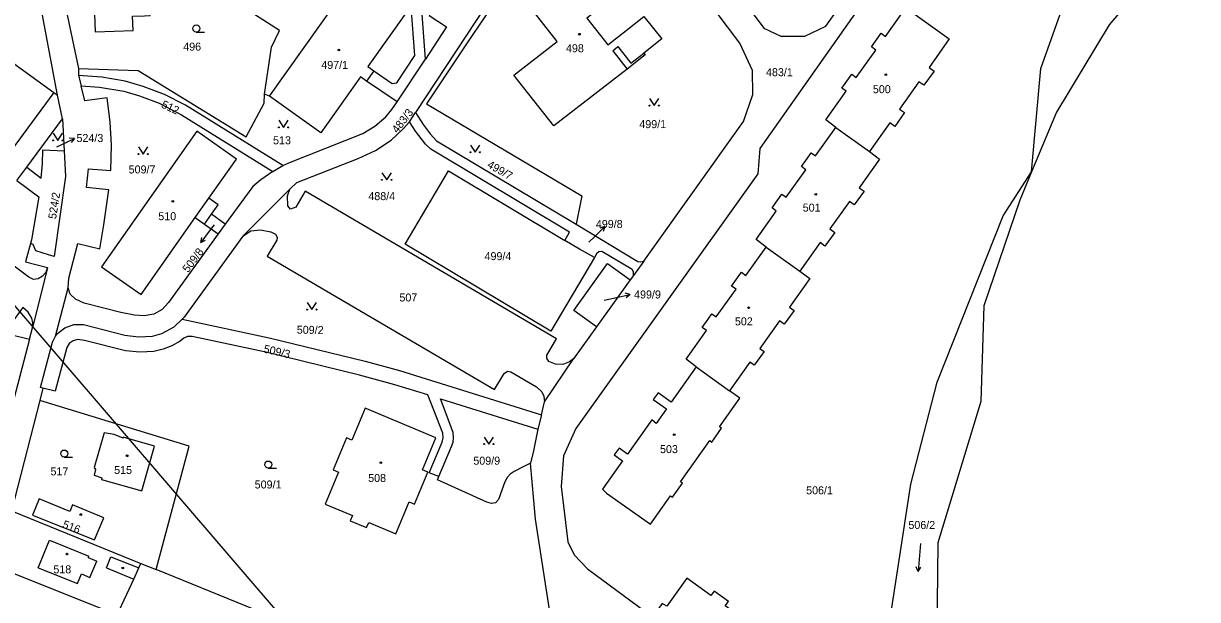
# Model space of a CAD drawing. Extents: x -558358 to -557517, y -1073785 to -1073189.
# Drawn here: x -558075.5 to -557826.1, y -1073555.9 to -1073433.5 of the extents above; entities that cross this region are included whole.
import ezdxf

# ---------------------------------------------------------------- set-up
doc = ezdxf.new("R2010")
doc.units = 0
for name, color, linetype in [('Hranice parcel', 7, 'Continuous'), ('Parcelní čísla', 7, 'Continuous'), ('Pop  PČ popisy', 7, 'Continuous'), ('Vnitřní kresba', 7, 'Continuous'), ('Vrstva 28', 7, 'Continuous'), ('Značky budov', 7, 'Continuous'), ('Značky kultur', 7, 'Continuous')]:
    doc.layers.add(name, color=color, linetype=linetype)

msp = doc.modelspace()

# ---------------------------------------------------------------- linework, layer by layer
at = {"layer": 'Hranice parcel'}
for p, q in [((-558068.26, -1073448.76), (-558079.07, -1073390.9)), ((-558069.9, -1073413.89), (-558063.79, -1073443.12)), ((-558079.09, -1073440.91), (-558069.01, -1073448.19)), ((-557996.12, -1073450.19), (-557990.11, -1073441.11)), ((-558063.79, -1073443.12), (-558063.8, -1073444.57)), ((-558063.8, -1073444.57), (-558063.26, -1073446.76)), ((-558001.05, -1073443.62), (-558002.62, -1073445.83)), ((-558001.05, -1073443.62), (-557997.16, -1073446.28)), ((-557996.12, -1073450.19), (-558002.62, -1073445.83)), ((-558069.01, -1073448.19), (-558068.26, -1073448.76)), ((-558067.19, -1073453.76), (-558068.26, -1073448.76)), ((-558023.22, -1073448.98), (-558024.27, -1073448.53)), ((-558074.8, -1073464.07), (-558067.19, -1073453.76)), ((-558067.19, -1073453.76), (-558066.82, -1073460.61)), ((-557993.5, -1073454.4), (-557992.19, -1073452.45)), ((-557902.93, -1073455.63), (-557895.8, -1073460.74)), ((-557987.76, -1073458.45), (-557958.11, -1073476.19)), ((-558071.37, -1073460.39), (-558066.82, -1073460.61)), ((-558076.9, -1073466.92), (-558074.8, -1073464.07)), ((-558074.8, -1073464.07), (-558071.72, -1073466.37)), ((-558022.54, -1073464.96), (-558020.42, -1073463.73)), ((-558076.9, -1073466.92), (-558072.2, -1073470.34)), ((-558018.89, -1073468.72), (-558028.88, -1073478.68)), ((-558072.2, -1073470.34), (-558073.77, -1073479.5)), ((-558037.01, -1073476.18), (-558035.54, -1073474.05)), ((-558032.65, -1073476.17), (-558035.54, -1073474.05)), ((-558037.01, -1073476.18), (-558034.12, -1073478.2)), ((-558032.65, -1073476.17), (-558034.12, -1073478.2)), ((-557958.11, -1073476.19), (-557944.96, -1073484.06)), ((-558073.77, -1073479.5), (-558073.98, -1073480.28)), ((-558073.98, -1073480.28), (-558075.03, -1073484.15)), ((-557917.76, -1073481.02), (-557910.62, -1073486.13)), ((-558075.03, -1073484.15), (-558070.38, -1073485.35)), ((-557958.62, -1073494.5), (-557951.44, -1073484.51)), ((-557951.44, -1073484.51), (-557946.6, -1073487.99)), ((-557943.74, -1073483.99), (-557945.94, -1073487.07)), ((-557944.96, -1073484.06), (-557944.51, -1073484.17)), ((-557944.51, -1073484.17), (-557943.74, -1073483.99)), ((-558070.38, -1073485.35), (-558073.57, -1073498.15)), ((-557945.94, -1073487.07), (-557946.6, -1073487.99)), ((-557945.94, -1073487.07), (-557945.95, -1073486.25)), ((-558068.7, -1073499.98), (-558066, -1073489.71)), ((-557946.6, -1073487.99), (-557953.75, -1073497.99)), ((-557953.75, -1073497.99), (-557958.62, -1073494.5)), ((-558078.27, -1073499.57), (-558074.22, -1073500.6)), ((-558074.22, -1073500.6), (-558073.57, -1073498.15)), ((-557953.75, -1073497.99), (-557958.67, -1073504.77)), ((-558074.22, -1073500.6), (-558078.34, -1073516.28)), ((-557964.79, -1073513.87), (-557958.67, -1073504.77)), ((-557932.61, -1073506.45), (-557925.51, -1073511.53)), ((-558071.35, -1073510.96), (-558072, -1073513.63)), ((-558071.35, -1073510.96), (-558071.87, -1073510.83)), ((-558068.72, -1073511.63), (-558071.35, -1073510.96)), ((-558072, -1073513.63), (-558078.01, -1073537.04)), ((-557965.43, -1073516.64), (-557964.79, -1073513.87)), ((-557872.13, -1073513.82), (-557881.3, -1073543.83)), ((-557965.43, -1073516.64), (-557966.22, -1073519.7)), ((-557966.22, -1073519.7), (-557967.17, -1073524.31)), ((-557967.17, -1073524.31), (-557967.76, -1073526.9)), ((-557967.76, -1073526.9), (-557969.49, -1073527.78)), ((-558078.01, -1073537.04), (-558050.57, -1073548.21)), ((-558080.96, -1073549.01), (-558055.56, -1073559.09)), ((-558050.57, -1073548.21), (-558047.33, -1073549.53))]:
    msp.add_line(p, q, dxfattribs=at)
for points in [[(-558022.09, -1073311.21), (-558020.08, -1073313.87), (-558000.41, -1073328.2), (-557993.92, -1073334.5), (-557986.04, -1073343.93), (-557967.1, -1073369.2), (-557918.24, -1073434.51), (-557914.64, -1073436.24), (-557909.55, -1073436.22), (-557905.05, -1073434.1), (-557902.57, -1073430.65), (-557891.22, -1073414.37), (-557877.97, -1073395.43)], [(-557997.16, -1073446.28), (-557996.18, -1073446.14), (-557992.37, -1073440.37), (-557993.13, -1073429.99), (-557993.58, -1073428.02), (-558004.25, -1073395), (-558005.55, -1073391.58), (-558006.57, -1073389.94), (-558009.69, -1073386.81), (-558015.69, -1073381.13), (-558022.86, -1073375.1), (-558038.38, -1073364.54), (-558051.46, -1073355.75)], [(-557861.36, -1073465.07), (-557859.38, -1073443.12), (-557853.44, -1073426.35), (-557845.8, -1073410.81), (-557826.12, -1073387.26)], [(-557990.11, -1073441.11), (-557990.95, -1073429.72), (-557991.6, -1073426.99), (-558000.34, -1073399.97), (-557986.42, -1073409.86), (-557979.13, -1073399.38), (-557977.23, -1073400.7), (-557975.75, -1073398.59), (-557966.19, -1073404.96)], [(-557943.74, -1073483.99), (-557922.57, -1073454.37), (-557920.54, -1073448.62), (-557920.67, -1073443.5), (-557923.32, -1073437.76), (-557933.57, -1073424.07), (-557935, -1073422.19), (-557950.81, -1073400.97)], [(-557966.19, -1073404.96), (-557967.15, -1073406.3), (-557970.9, -1073403.86), (-557989.34, -1073431.82), (-557985.62, -1073434.28), (-557990.11, -1073441.11)], [(-557960.73, -1073418.81), (-557955.07, -1073414.41), (-557951.22, -1073411.42), (-557950.93, -1073411.8), (-557947.21, -1073416.59), (-557951.08, -1073419.63), (-557946.63, -1073425.3), (-557955.8, -1073432.39), (-557951.37, -1073438.08), (-557947.44, -1073435.04), (-557943.73, -1073432.04), (-557939.89, -1073436.78), (-557943.7, -1073439.86), (-557943.42, -1073440.21), (-557947.29, -1073443.23), (-557962.81, -1073455.3), (-557971.36, -1073444.52), (-557962.13, -1073437.38), (-557970.6, -1073426.47), (-557970.03, -1073426.04)], [(-557875.08, -1073418.52), (-557880.11, -1073415), (-557884.66, -1073414.11), (-557888.78, -1073417.07), (-557919.08, -1073460.09), (-557919.51, -1073465.45), (-557958.15, -1073519.56), (-557960.76, -1073525.37), (-557961.25, -1073531.9), (-557959.85, -1073543.64), (-557958.52, -1073546.41), (-557955.67, -1073549.33), (-557941.9, -1073559.58)], [(-557968.81, -1073419.39), (-557969.8, -1073419.14), (-557970.66, -1073419.77), (-557992.19, -1073452.45)], [(-558049.8, -1073431.93), (-558048.54, -1073431.88), (-558048.64, -1073429.15), (-558049.91, -1073429.2), (-558050.08, -1073422.86), (-558052.56, -1073422.66), (-558052.57, -1073422.02), (-558060.76, -1073422.24), (-558060.26, -1073435.32), (-558052.21, -1073435.02), (-558052.32, -1073432.02), (-558049.8, -1073431.93)], [(-557834.15, -1073421.11), (-557844.86, -1073433.81), (-557856.07, -1073452.41), (-557861.36, -1073465.07)], [(-558023.22, -1073448.98), (-558004.82, -1073423.06), (-557993.94, -1073430.83), (-558002.36, -1073442.69), (-558001.05, -1073443.62)], [(-557971.99, -1073423.64), (-557977.49, -1073432.15), (-557981.25, -1073437.64), (-557989.89, -1073450.63)], [(-558024.27, -1073448.53), (-558022.77, -1073438.58), (-558021.1, -1073435.02), (-558027.22, -1073431.17)], [(-557902.93, -1073455.63), (-557905.05, -1073454), (-557900.72, -1073447.94), (-557901.66, -1073447.27), (-557899.55, -1073444.33), (-557898.62, -1073444.99), (-557894.46, -1073439.18), (-557895.4, -1073438.51), (-557893.33, -1073435.61), (-557892.39, -1073436.28), (-557888.07, -1073430.23), (-557878.84, -1073436.82), (-557883.15, -1073442.9), (-557882.08, -1073443.65), (-557884.22, -1073446.66), (-557885.28, -1073445.91), (-557889.41, -1073451.73), (-557888.35, -1073452.48), (-557890.43, -1073455.41), (-557891.49, -1073454.66), (-557895.8, -1073460.74)], [(-558020.42, -1073463.73), (-558041.1, -1073450.88), (-558045.53, -1073448.61), (-558050.06, -1073446.9), (-558053.87, -1073445.77), (-558058.84, -1073444.97), (-558063.8, -1073444.57)], [(-558063.79, -1073443.12), (-558051.12, -1073443.51), (-558028.21, -1073457.62), (-558024.35, -1073450.45), (-558024.27, -1073448.53)], [(-558002.62, -1073445.83), (-558003.93, -1073444.91), (-558012.33, -1073456.75), (-558023.22, -1073448.98)], [(-558066, -1073489.71), (-558065.83, -1073487.66), (-558063.93, -1073480.27), (-558059.28, -1073481.39), (-558058.41, -1073476.28), (-558057.32, -1073468.85), (-558062.09, -1073468.41), (-558061.69, -1073464.41), (-558056.9, -1073464.79), (-558056.8, -1073459.32), (-558057.06, -1073454.51), (-558057.72, -1073449.34), (-558062.47, -1073450), (-558063.26, -1073446.76)], [(-558063.26, -1073446.76), (-558059.34, -1073447.1), (-558054.18, -1073447.94), (-558050.82, -1073448.92), (-558046.65, -1073450.5), (-558041.92, -1073452.93), (-558022.54, -1073464.96)], [(-558069.01, -1073448.19), (-558089.39, -1073475.8), (-558089.17, -1073475.95), (-558090.09, -1073477.27), (-558100.29, -1073469.58), (-558095.61, -1073463.24)], [(-558020.42, -1073463.73), (-558018.76, -1073463.03), (-558003.4, -1073456.89), (-558000.84, -1073455.32), (-557998.53, -1073453.34), (-557997.26, -1073451.83), (-557996.12, -1073450.19)], [(-557989.89, -1073450.63), (-557956.91, -1073470.13), (-557958.11, -1073476.19)], [(-558018.89, -1073468.72), (-558017.43, -1073467.28), (-558004.36, -1073462.2), (-558000.71, -1073460.54), (-557997.38, -1073458.33), (-557994.81, -1073455.9), (-557993.5, -1073454.4)], [(-557960.53, -1073479.61), (-557959.52, -1073477.88), (-557988.99, -1073460.22), (-557990.09, -1073459.14), (-557992.19, -1073456.42), (-557993.5, -1073454.4)], [(-557992.19, -1073452.45), (-557990.57, -1073454.98), (-557989.11, -1073456.98), (-557987.76, -1073458.45)], [(-558035.54, -1073474.05), (-558034.14, -1073472.03), (-558036.08, -1073470.66), (-558030.24, -1073462.37), (-558038.66, -1073456.4), (-558058.9, -1073485.25), (-558050.49, -1073491.12), (-558038.98, -1073474.78), (-558037.01, -1073476.18)], [(-557917.76, -1073481.02), (-557919.89, -1073479.42), (-557915.58, -1073473.37), (-557916.49, -1073472.72), (-557914.4, -1073469.79), (-557913.49, -1073470.44), (-557909.33, -1073464.6), (-557910.24, -1073463.95), (-557908.96, -1073462.17), (-557908.15, -1073461.02), (-557907.24, -1073461.67), (-557902.93, -1073455.63)], [(-558066.82, -1073460.61), (-558066.53, -1073466.05), (-558068.98, -1073483.05), (-558070.17, -1073482.68), (-558072.89, -1073481.86), (-558073.42, -1073480.5), (-558073.98, -1073480.28)], [(-558071.72, -1073466.37), (-558071.45, -1073463.36), (-558071.37, -1073460.39)], [(-557895.8, -1073460.74), (-557893.65, -1073462.39), (-557897.97, -1073468.43), (-557896.94, -1073469.17), (-557899.02, -1073472.08), (-557900.05, -1073471.34), (-557904.22, -1073477.17), (-557903.16, -1073477.93), (-557905.25, -1073480.84), (-557906.3, -1073480.09), (-557910.62, -1073486.13)], [(-557954.23, -1073483.22), (-557963.48, -1073498.87), (-557994.38, -1073480.4), (-557985.2, -1073464.81), (-557960.53, -1073479.61)], [(-558022.54, -1073464.96), (-558025.08, -1073466.74), (-558026.8, -1073468.19), (-558032.65, -1073476.17)], [(-557897.48, -1073592.57), (-557892.38, -1073566.43), (-557887.02, -1073531.37), (-557881.44, -1073509.74), (-557867.37, -1073474.4), (-557861.36, -1073465.07)], [(-557861.36, -1073465.07), (-557863.88, -1073471.1), (-557871.54, -1073493.51), (-557872.13, -1073513.82)], [(-557958.67, -1073504.77), (-557959.52, -1073505.42), (-557960.94, -1073505.97), (-557962.48, -1073505.9), (-557963.93, -1073505.3), (-557964.34, -1073504.64), (-557964.29, -1073503.98), (-557962.25, -1073500.52), (-558015.64, -1073469.14), (-558017.62, -1073472.56), (-558018.8, -1073472.98), (-558019.32, -1073472.29), (-558019.38, -1073470.18), (-558018.89, -1073468.72)], [(-558073.57, -1073498.15), (-558073.51, -1073497.13), (-558073.7, -1073496.11), (-558074.52, -1073494.85), (-558075.64, -1073493.89), (-558078.28, -1073497.56), (-558092.71, -1073486.96), (-558086.45, -1073478.46)], [(-558070.38, -1073485.35), (-558070.76, -1073486.43), (-558071.41, -1073487.24), (-558072.33, -1073487.8), (-558073.38, -1073487.88), (-558074.36, -1073487.41), (-558086.45, -1073478.46)], [(-558034.12, -1073478.2), (-558044.67, -1073492.79), (-558046.03, -1073494.25), (-558047.82, -1073495.28), (-558049.88, -1073495.66), (-558051.92, -1073495.51), (-558054.81, -1073494.91), (-558062.59, -1073492.91), (-558064.44, -1073492.11), (-558065.56, -1073491.04), (-558066, -1073489.71)], [(-558028.88, -1073478.68), (-558041.38, -1073495.88), (-558041.79, -1073496.35)], [(-558028.88, -1073478.68), (-558027.22, -1073477.58), (-558025.14, -1073477.37), (-558022.91, -1073477.77), (-558021.94, -1073478.27), (-558021.58, -1073478.9), (-558021.69, -1073479.54), (-558023.7, -1073482.95), (-557975.42, -1073511.29), (-557973.41, -1073507.84), (-557972.71, -1073507.36), (-557971.95, -1073507.53), (-557966.49, -1073510.72), (-557965.39, -1073511.77), (-557964.96, -1073512.7), (-557964.79, -1073513.87)], [(-557954.23, -1073483.22), (-557957.38, -1073481.46), (-557960.53, -1073479.61)], [(-557945.95, -1073486.25), (-557946.2, -1073485.81), (-557952.65, -1073481.96), (-557953.3, -1073482.07), (-557953.78, -1073482.47), (-557954.23, -1073483.22)], [(-557932.61, -1073506.45), (-557934.75, -1073504.84), (-557930.41, -1073498.76), (-557931.35, -1073498.09), (-557930.07, -1073496.31), (-557929.28, -1073495.19), (-557928.34, -1073495.86), (-557924.14, -1073489.96), (-557925.07, -1073489.3), (-557922.99, -1073486.39), (-557922.06, -1073487.05), (-557917.76, -1073481.02)], [(-557910.62, -1073486.13), (-557908.48, -1073487.72), (-557912.81, -1073493.77), (-557911.82, -1073494.47), (-557913.92, -1073497.39), (-557914.9, -1073496.69), (-557919.09, -1073502.55), (-557918.19, -1073503.19), (-557920.29, -1073506.11), (-557921.18, -1073505.47), (-557925.51, -1073511.53)], [(-558068.7, -1073499.98), (-558068.26, -1073499.37), (-558066.7, -1073498.15), (-558064.79, -1073497.48), (-558062.72, -1073497.49), (-558053.98, -1073499.73), (-558051.03, -1073500.12), (-558048.06, -1073499.96), (-558046.1, -1073499.41), (-558043.49, -1073497.93), (-558041.79, -1073496.35)], [(-558041.79, -1073496.35), (-558023.3, -1073500.28), (-558002.91, -1073505.27), (-557995.6, -1073507.26), (-557965.43, -1073516.64)], [(-558071.87, -1073510.83), (-558069.32, -1073501.19), (-558068.7, -1073499.98)], [(-557987.27, -1073529.77), (-557989.29, -1073528.94), (-557986.56, -1073522.48), (-557986.36, -1073521.52), (-557986.44, -1073520.51), (-557989.6, -1073512.4), (-557996.64, -1073510.25), (-558004.14, -1073508.22), (-558024.01, -1073503.35), (-558039.66, -1073500.03), (-558040.64, -1073500.03), (-558041.42, -1073500.4), (-558042.23, -1073501), (-558043.97, -1073502.01), (-558045.84, -1073502.74), (-558047.8, -1073503.22), (-558050.8, -1073503.37), (-558053.79, -1073503.03), (-558062.52, -1073500.9), (-558063.99, -1073500.68), (-558064.96, -1073500.91), (-558065.77, -1073501.48), (-558066.28, -1073502.33), (-558068.72, -1073511.63)], [(-557932.61, -1073506.45), (-557937.92, -1073513.94), (-557940.69, -1073511.97), (-557941.71, -1073513.4), (-557938.93, -1073515.37), (-557941.12, -1073518.46), (-557942.01, -1073517.7), (-557947.21, -1073524.97), (-557948.97, -1073523.73), (-557949.99, -1073525.17), (-557948.24, -1073526.41), (-557952.49, -1073532.47), (-557951.63, -1073533.27), (-557942.33, -1073539.86), (-557938.05, -1073533.83), (-557937.62, -1073534.14), (-557935.52, -1073531.19), (-557935.95, -1073530.88), (-557929.72, -1073522.11), (-557929.27, -1073522.43), (-557927.19, -1073519.5), (-557927.64, -1073519.19), (-557923.33, -1073513.13), (-557925.51, -1073511.53)], [(-558047.33, -1073549.53), (-558040.31, -1073523.33), (-558072, -1073513.63)], [(-557987.27, -1073529.77), (-557984.55, -1073523.36), (-557984.23, -1073522.42), (-557984.14, -1073521.45), (-557984.2, -1073520.39), (-557986.94, -1073513.23), (-557966.22, -1073519.7)], [(-558008.57, -1073528.8), (-558011.42, -1073535.59), (-558005.63, -1073538.02), (-558006.1, -1073539.13), (-558002.62, -1073540.59), (-558002.16, -1073539.49), (-557996.41, -1073541.91), (-557993.56, -1073535.14), (-557992.45, -1073535.6), (-557989.61, -1073528.81), (-557990.71, -1073528.34), (-557987.91, -1073521.54), (-558002.9, -1073515.24), (-558005.74, -1073522.02), (-558006.84, -1073521.56), (-558009.68, -1073528.33), (-558008.57, -1073528.8)], [(-558060.16, -1073528.26), (-558060.48, -1073529.48), (-558058.86, -1073530.06), (-558058.94, -1073530.35), (-558050.37, -1073532.81), (-558047.63, -1073523.32), (-558054.29, -1073521.4), (-558054.34, -1073521.59), (-558056.23, -1073520.85), (-558058.32, -1073520.45), (-558060.47, -1073527.85), (-558060.16, -1073528.26)], [(-557961.12, -1073576.24), (-557962.13, -1073568.62), (-557962.94, -1073563.5), (-557966.76, -1073538.79), (-557967.76, -1073526.9)], [(-557969.49, -1073527.78), (-557971.24, -1073528.71), (-557972.09, -1073529.24), (-557972.78, -1073529.97), (-557973.26, -1073530.86), (-557974.57, -1073534.63), (-557975.26, -1073535.31), (-557976.1, -1073535.45), (-557977.05, -1073535.17), (-557987.55, -1073530.47), (-557987.27, -1073529.77)], [(-558058.43, -1073538.53), (-558065.06, -1073535.79), (-558065.61, -1073537.16), (-558072.15, -1073534.51), (-558073.59, -1073537.94), (-558060.37, -1073543.23), (-558058.43, -1073538.53)], [(-557881.3, -1073543.83), (-557881.54, -1073569.39), (-557886.18, -1073582.51)], [(-558055.56, -1073559.09), (-558052.02, -1073551.52), (-558051, -1073549.15), (-558050.57, -1073548.21)], [(-557977.41, -1073591.02), (-557981.5, -1073577.12), (-557984.25, -1073575.17), (-558047.33, -1073549.53)], [(-557944.07, -1073562.64), (-557943.15, -1073563.3), (-557947.42, -1073569.28), (-557934.16, -1073578.7), (-557929.93, -1073572.77), (-557928.96, -1073573.46), (-557924.72, -1073567.52), (-557925.63, -1073566.74), (-557921.33, -1073560.9), (-557926.44, -1073557.23), (-557925.76, -1073556.27), (-557928.81, -1073554.08), (-557929.5, -1073555.03), (-557934.61, -1073551.36), (-557938.85, -1073557.29), (-557939.81, -1073556.68), (-557941.9, -1073559.58)]]:
    msp.add_lwpolyline(points, dxfattribs=at)
at = {"layer": 'Pop  PČ popisy'}
for p, q in [((-558068.37, -1073459.77), (-558067.34, -1073459.26)), ((-558067.34, -1073459.26), (-558064.64, -1073457.94)), ((-558064.64, -1073457.94), (-558065.76, -1073457.93)), ((-558064.64, -1073457.94), (-558065.32, -1073458.83)), ((-558035, -1073476.29), (-558036.02, -1073477.67)), ((-557954.15, -1073478.76), (-557951.99, -1073476.68)), ((-557951.99, -1073476.68), (-557953.06, -1073477.01)), ((-557951.99, -1073476.68), (-557952.36, -1073477.73)), ((-558036.02, -1073477.67), (-558037.83, -1073480.07)), ((-558037.83, -1073480.07), (-558037.62, -1073478.97)), ((-558037.83, -1073480.07), (-558036.82, -1073479.57)), ((-557955.41, -1073479.99), (-557954.15, -1073478.76)), ((-557952.15, -1073492.28), (-557949.53, -1073491.73)), ((-557949.53, -1073491.73), (-557946.59, -1073491.11)), ((-557946.59, -1073491.11), (-557947.68, -1073490.82)), ((-557946.59, -1073491.11), (-557947.47, -1073491.8))]:
    msp.add_line(p, q, dxfattribs=at)
at = {"layer": 'Vnitřní kresba'}
for p, q in [((-557950.33, -1073439.32), (-557949.26, -1073438.42)), ((-557950.33, -1073439.32), (-557947.29, -1073443.23)), ((-557949.26, -1073438.42), (-557946.5, -1073442)), ((-557946.5, -1073442), (-557943.7, -1073439.86)), ((-558038.98, -1073474.78), (-558036.08, -1073470.66)), ((-558072.33, -1073549.11), (-558069.95, -1073543.28)), ((-558069.95, -1073543.28), (-558061.62, -1073546.69)), ((-558061.73, -1073546.96), (-558061.62, -1073546.69)), ((-558061.73, -1073546.96), (-558059.91, -1073547.71)), ((-558057.87, -1073549.14), (-558056.91, -1073546.78)), ((-558056.91, -1073546.78), (-558051, -1073549.15)), ((-558072.33, -1073549.11), (-558064.04, -1073552.48)), ((-558061.37, -1073551.16), (-558059.91, -1073547.71)), ((-558057.87, -1073549.14), (-558052.02, -1073551.52)), ((-558064.04, -1073552.48), (-558063.17, -1073550.4)), ((-558063.17, -1073550.4), (-558061.37, -1073551.16))]:
    msp.add_line(p, q, dxfattribs=at)
at = {"layer": 'Vrstva 28'}
msp.add_line((-558150.5, -1073408.33), (-557941.76, -1073651.48), dxfattribs=at)
at = {"layer": 'Značky budov'}
for centre in [(-557957.4, -1073435.82), (-558008.5, -1073439.16), (-557892.32, -1073444.4), (-557907.2, -1073469.84), (-558043.77, -1073471.33), (-557921.47, -1073493.92), (-557937.27, -1073520.85), (-558053.47, -1073525.34), (-557999.58, -1073526.81), (-558063.31, -1073537.83), (-558066.22, -1073546.23), (-558054.38, -1073549.16)]:
    msp.add_circle(centre, 0.175, dxfattribs=at)
at = {"layer": 'Značky kultur'}
for p, q in [((-558038.77, -1073435.36), (-558037.02, -1073435.36)), ((-558066.82, -1073525.63), (-558065.07, -1073525.63)), ((-558023.49, -1073527.96), (-558021.74, -1073527.96)), ((-557884.95, -1073543.96), (-557885.47, -1073549.94)), ((-557885.47, -1073549.94), (-557885.89, -1073548.92)), ((-557885.47, -1073549.94), (-557884.89, -1073549.01))]:
    msp.add_line(p, q, dxfattribs=at)
for points in [[(-557942.51, -1073449.49), (-557941.51, -1073450.99), (-557940.51, -1073449.49)], [(-558021.24, -1073454.11), (-558020.24, -1073455.61), (-558019.24, -1073454.11)], [(-558069.21, -1073456.87), (-558068.21, -1073458.37), (-558067.21, -1073456.87)], [(-558051.07, -1073459.77), (-558050.07, -1073461.27), (-558049.07, -1073459.77)], [(-557980.53, -1073459.39), (-557979.53, -1073460.89), (-557978.53, -1073459.39)], [(-557999.34, -1073465.25), (-557998.34, -1073466.75), (-557997.34, -1073465.25)], [(-558015.26, -1073492.81), (-558014.26, -1073494.31), (-558013.26, -1073492.81)], [(-557977.66, -1073521.36), (-557976.66, -1073522.86), (-557975.66, -1073521.36)]]:
    msp.add_lwpolyline(points, dxfattribs=at)
for centre, radius in [((-558038.77, -1073434.61), 0.75), ((-557942.51, -1073450.99), 0.1), ((-557940.51, -1073450.99), 0.1), ((-558021.24, -1073455.61), 0.1), ((-558019.24, -1073455.61), 0.1), ((-558069.21, -1073458.37), 0.1), ((-558067.21, -1073458.37), 0.1), ((-558051.07, -1073461.27), 0.1), ((-558049.07, -1073461.27), 0.1), ((-557980.53, -1073460.89), 0.1), ((-557978.53, -1073460.89), 0.1), ((-557999.34, -1073466.75), 0.1), ((-557997.34, -1073466.75), 0.1), ((-558015.26, -1073494.31), 0.1), ((-558013.26, -1073494.31), 0.1), ((-558066.82, -1073524.88), 0.75), ((-557977.66, -1073522.86), 0.1), ((-557975.66, -1073522.86), 0.1), ((-558023.49, -1073527.21), 0.75)]:
    msp.add_circle(centre, radius, dxfattribs=at)

# ---------------------------------------------------------------- texts
at = {"layer": 'Parcelní čísla'}
for s, p in [('496', (-558041.55, -1073439.31)), ('498', (-557960.26, -1073439.66)), ('497/1', (-558012.23, -1073443.2)), ('483/1', (-557917.77, -1073444.74)), ('500', (-557895.07, -1073448.35)), ('499/1', (-557944.68, -1073455.77)), ('524/3', (-558064.22, -1073458.72)), ('513', (-558022.47, -1073459.2)), ('509/7', (-558053.14, -1073465.39)), ('488/4', (-558002.23, -1073471.06)), ('501', (-557909.97, -1073473.5)), ('510', (-558046.84, -1073475.32)), ('499/8', (-557953.91, -1073476.98)), ('499/4', (-557977.55, -1073483.8)), ('507', (-557995.63, -1073492.58)), ('499/9', (-557945.79, -1073491.94)), ('502', (-557924.38, -1073497.65)), ('503', (-557940.28, -1073524.78)), ('509/9', (-557979.93, -1073527.24)), ('517', (-558069.74, -1073529.5)), ('515', (-558056.22, -1073529.21)), ('508', (-558002.27, -1073530.91)), ('509/1', (-558026.37, -1073532.29)), ('506/1', (-557909.25, -1073533.53)), ('506/2', (-557887.53, -1073540.89)), ('518', (-558069.13, -1073550.31))]:
    msp.add_text(s, height=1.7, dxfattribs=at).set_placement(p)
for s, rotation, p in [('512', 335, (-558046.36, -1073451.33)), ('483/3', 52, (-557996.07, -1073456.97)), ('499/7', 330, (-557977.15, -1073463.99)), ('524/2', 81, (-558068.56, -1073475.16)), ('509/8', 53, (-558040.52, -1073486.58)), ('509/2', 359, (-558017.44, -1073499.41)), ('509/3', 347, (-558024.6, -1073503.39)), ('516', 339, (-558067.34, -1073540.57))]:
    msp.add_text(s, height=1.7, rotation=rotation, dxfattribs=at).set_placement(p)

doc.saveas('drawing.dxf')
